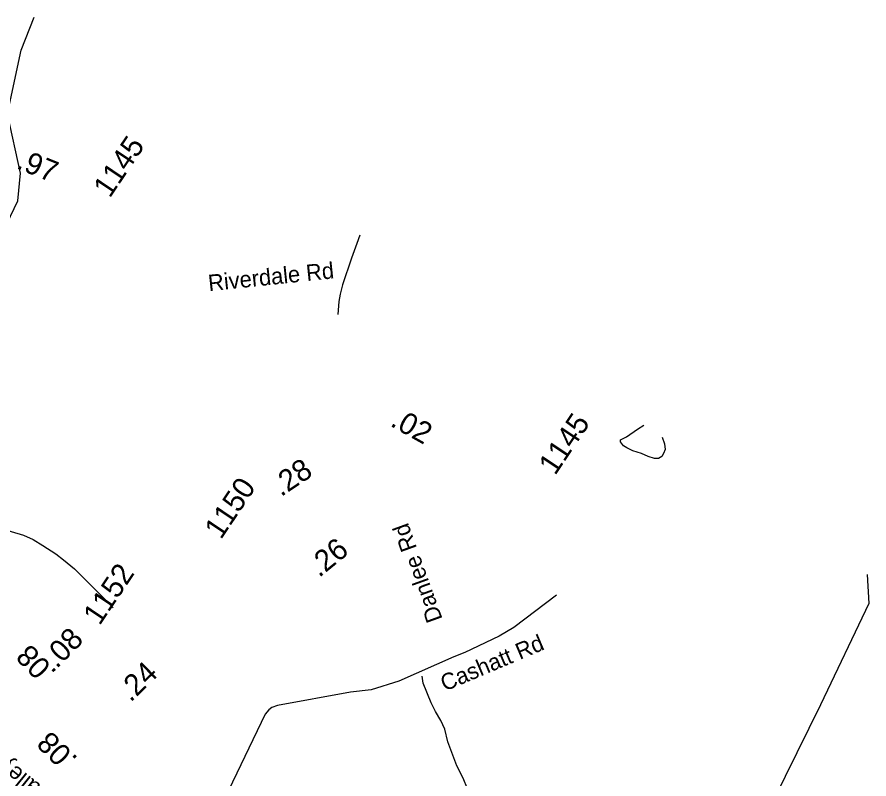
# Model space of a CAD drawing. Extents: x 1716282 to 1717158, y 799307 to 801078.
# Drawn here: x 1716976.7 to 1717048.5, y 800972.8 to 801037 of the extents above; entities that cross this region are included whole.
import ezdxf

# ---------------------------------------------------------------- set-up
doc = ezdxf.new("R2010")
doc.units = 0
for name, color, linetype in [('Exist Hydrographic Misc Water Feature', 7, 'Continuous'), ('Exist Hydrographic Pond Under 1500 Sq Ft', 7, 'Continuous'), ('Exist Road Non-System Type 51', 7, 'Continuous'), ('Exist Road Non-System Type 51 Label', 7, 'Continuous'), ('Exist Road Secondary Mileage Hundredths English Label', 7, 'Continuous'), ('Exist Road Secondary Type 51 Label', 7, 'Continuous'), ('Exist Road Secondary Type 51 Number Label', 7, 'Continuous'), ('Exist Utilities Electrical Transmission Line', 7, 'Continuous')]:
    doc.layers.add(name, color=color, linetype=linetype)

msp = doc.modelspace()

# ---------------------------------------------------------------- linework, layer by layer
at = {"layer": 'Exist Hydrographic Misc Water Feature'}
for points in [[(1716946.337, 800967.985), (1716954.984, 800968.809), (1716956.616, 800969.899), (1716958.929, 800973.289), (1716959.641, 800975.885), (1716960.09, 800981.427), (1716961.275, 800984.284), (1716964.34, 800988.336), (1716966.584, 800997.774), (1716966.693, 801000.338), (1716963.968, 801009.228), (1716963.543, 801012.443), (1716963.891, 801014.847), (1716964.635, 801015.497), (1716966.163, 801015.191), (1716974.711, 801018.281), (1716975.611, 801018.988), (1716976.81, 801021.535), (1716977.042, 801023.859), (1716975.945, 801028.85), (1716977.091, 801034.226), (1716978.196, 801037.014)], [(1717005.636, 801018.648), (1717005.371, 801017.946), (1717004.913, 801016.71), (1717004.173, 801014.444), (1717003.963, 801013.672), (1717003.851, 801013.046), (1717003.768, 801011.946)], [(1716967.459, 800998.137), (1716968.177, 800997.438), (1716969.412, 800996.315), (1716970.04, 800995.848), (1716970.64, 800995.439), (1716971.584, 800994.969), (1716972.314, 800994.648), (1716973.107, 800994.318), (1716973.997, 800994.13), (1716974.744, 800994.041), (1716975.482, 800993.887), (1716976.253, 800993.679), (1716977.271, 800993.37), (1716978.096, 800992.982), (1716978.918, 800992.489), (1716980.013, 800991.777), (1716980.668, 800991.296), (1716981.584, 800990.529), (1716984.003, 800988.105), (1716984.852, 800987.24)], [(1717018.064, 800961.393), (1717017.865, 800962.232), (1717017.788, 800963.303), (1717017.719, 800964.229), (1717017.245, 800965.852), (1717016.845, 800966.653), (1717016.473, 800967.292), (1717015.795, 800968.562), (1717015.381, 800969.55), (1717015.036, 800970.383), (1717014.923, 800971.092), (1717014.691, 800971.987), (1717014.316, 800972.878), (1717013.805, 800973.929), (1717013.048, 800975.957), (1717012.785, 800977.013), (1717012.439, 800977.741), (1717012.005, 800978.493), (1717011.635, 800979.238), (1717010.947, 800980.905), (1717010.88, 800981.475)]]:
    msp.add_lwpolyline(points, dxfattribs=at)
at = {"layer": 'Exist Hydrographic Pond Under 1500 Sq Ft'}
for points in [[(1717027.583, 801001.401), (1717028.101, 801001.644), (1717029.025, 801002.278), (1717029.564, 801002.633)], [(1717031.098, 801001.606), (1717031.281, 801001.055), (1717031.347, 801000.585), (1717031.223, 801000.249), (1717031.082, 800999.993), (1717030.784, 800999.813), (1717030.446, 800999.832), (1717029.916, 800999.983), (1717029.347, 801000.231), (1717028.635, 801000.472), (1717028.107, 801000.728), (1717027.827, 801000.883), (1717027.597, 801001.216), (1717027.583, 801001.401)]]:
    msp.add_lwpolyline(points, dxfattribs=at)
at = {"layer": 'Exist Road Non-System Type 51'}
msp.add_lwpolyline([(1717022.183, 800988.295), (1717018.59, 800985.588), (1717017.359, 800984.837), (1717014.474, 800983.475), (1717013.533, 800983.117), (1717008.897, 800981.053), (1717006.581, 800980.337), (1717004.839, 800980.138), (1716998.683, 800979.006), (1716998.204, 800978.831), (1716997.949, 800978.649), (1716997.64, 800978.288), (1716990.45, 800963.299), (1716989.475, 800961.136)], dxfattribs=at)
at = {"layer": 'Exist Utilities Electrical Transmission Line'}
msp.add_lwpolyline([(1717048.363, 800990.05), (1717048.521, 800987.617), (1717044.446, 800979.058), (1717038.49, 800966.994), (1717035.763, 800961.655), (1717032.383, 800954.971), (1717028.546, 800947.158), (1717024.077, 800937.874), (1717020.928, 800931.211), (1717016.764, 800922.672)], dxfattribs=at)

# ---------------------------------------------------------------- texts
at = {"layer": 'Exist Road Non-System Type 51 Label'}
msp.add_text('Danlee Rd', height=1.3775, rotation=109.85489, dxfattribs=at).set_placement((1717012.611, 800986.297))
at = {"layer": 'Exist Road Secondary Mileage Hundredths English Label'}
for s, rotation, p in [('.97', 338.11175, (1716976.6, 801024.292)), ('.02', 330.80515, (1717008.106, 801002.606)), ('.28', 34.12786, (1716998.986, 800996.557)), ('.26', 39.23081, (1717002.194, 800989.741)), ('.08', 45.61569, (1716980.084, 800982.065)), ('.08', 133.90369, (1716980.164, 800981.853)), ('.24', 44.08762, (1716986.308, 800979.229)), ('.08', 134.78275, (1716981.926, 800974.57))]:
    msp.add_text(s, height=1.8125, rotation=rotation, dxfattribs=at).set_placement(p)
at = {"layer": 'Exist Road Secondary Type 51 Label'}
for s, rotation, p in [('Riverdale Rd', 5.91719, (1716992.913, 801013.91)), ('Cashatt Rd', 22.87759, (1717012.779, 800980.183)), ('Kersey Valley Rd', 141.23728, (1716984.633, 800967.6))]:
    msp.add_text(s, height=1.3775, rotation=rotation, dxfattribs=at).set_placement(p)
at = {"layer": 'Exist Road Secondary Type 51 Number Label'}
for s, p in [('1145', (1716984.556, 801021.699)), ('1145', (1717022.077, 800998.337)), ('1150', (1716993.921, 800992.932)), ('1152', (1716983.697, 800985.687))]:
    msp.add_text(s, height=1.8125, rotation=56.20506, dxfattribs=at).set_placement(p)

doc.saveas('drawing.dxf')
